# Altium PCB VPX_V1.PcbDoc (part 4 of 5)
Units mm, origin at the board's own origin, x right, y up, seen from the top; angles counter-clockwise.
Board outline 157.76 x 100.08 mm, 10 copper layers (Top Layer (PADS/SIG), Layer 2 (GND), Layer 3 (SIG), Layer 4 (SIG), Layer 5 (GND), Layer 6 (PWR), Layer 7 (GND), Layer 8 (SIG/PWR), Layer 9 (GND), Bottom Layer (PAD/SIG)), stack 1.614 mm thick; 383 components, 223 nets, 1313 pads, 1223 vias.
Unrouted connection lines stored in the file: 3.
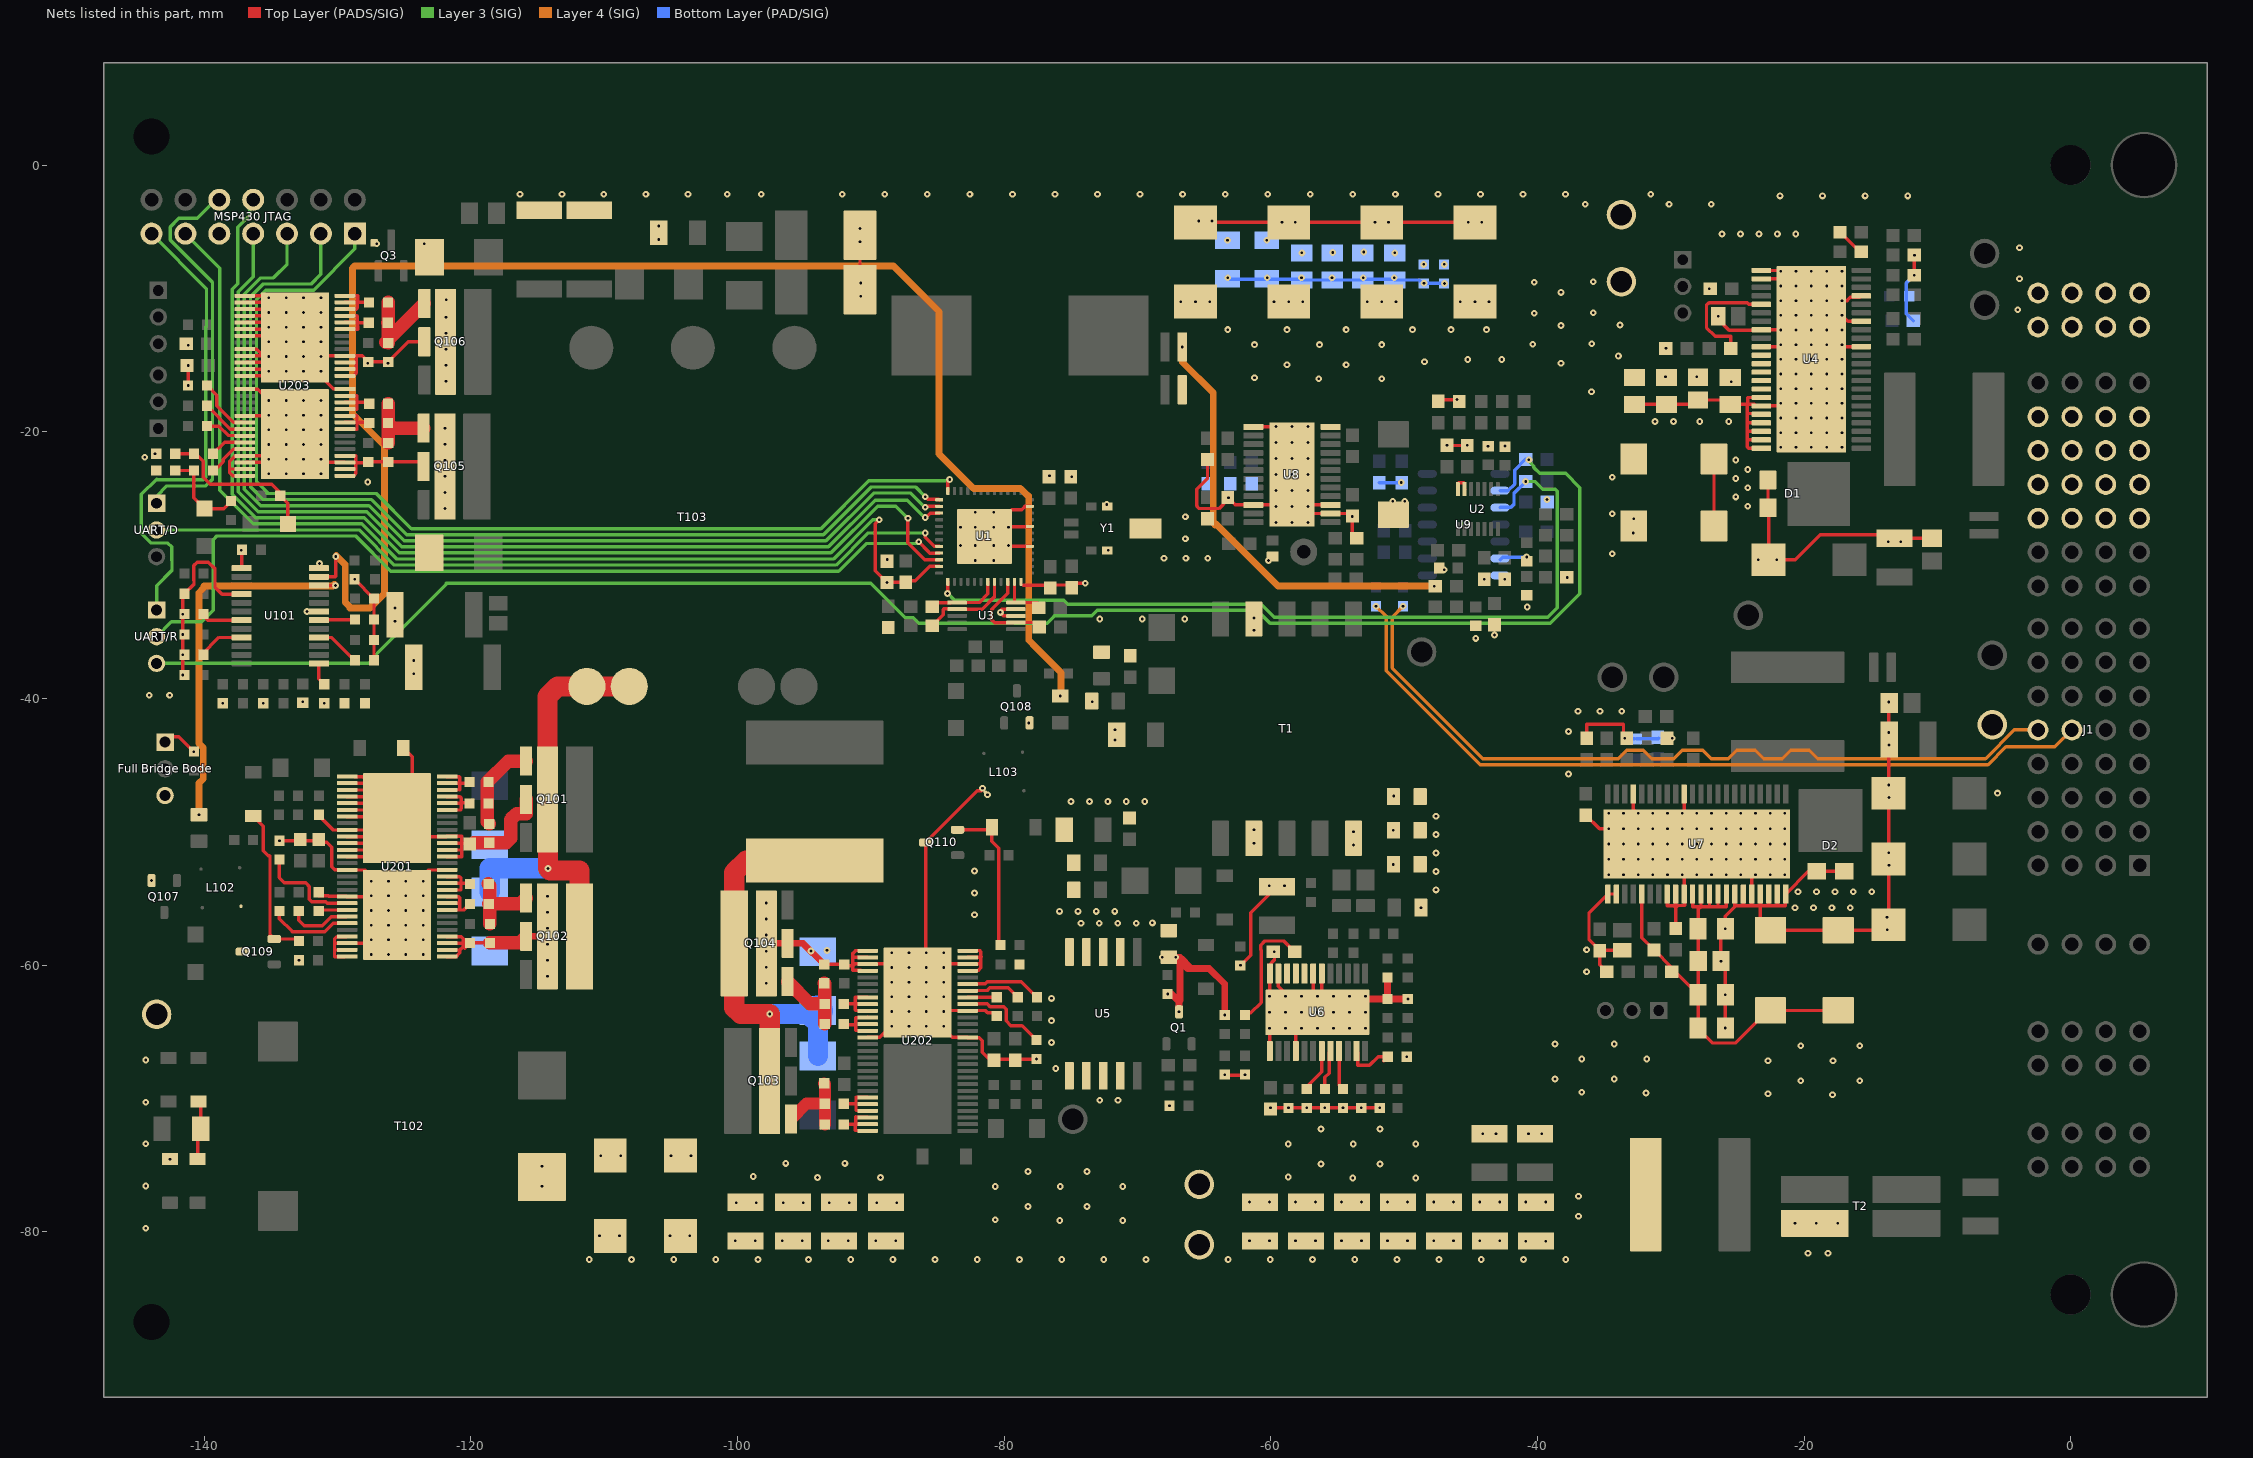
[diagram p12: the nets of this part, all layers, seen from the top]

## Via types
v1: diameter 0.508, hole 0.203, Top Layer (PADS/SIG) to Bottom Layer (PAD/SIG), 943 vias
v2: diameter 0.5, hole 0.2, Top Layer (PADS/SIG) to Bottom Layer (PAD/SIG), tented both sides, 268 vias
v3: diameter 0.5, hole 0.2, Top Layer (PADS/SIG) to Bottom Layer (PAD/SIG), 12 vias

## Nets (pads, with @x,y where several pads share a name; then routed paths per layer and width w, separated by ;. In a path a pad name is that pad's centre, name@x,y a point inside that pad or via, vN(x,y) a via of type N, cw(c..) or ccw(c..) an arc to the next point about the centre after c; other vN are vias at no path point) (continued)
NetR104_1: R104.1 U101.4 | length 3.4
  Top Layer (PADS/SIG) w0.254: U101.4@-131.381,-35.431 -130.447,-35.431 -128.741,-37.137 R104.1@-128.678,-37.137
NetR105_1: R105.1 U101.1 | length 1.7
  Top Layer (PADS/SIG) w0.254: U101.1@-131.381,-37.381 -131.381,-38.535 R105.1@-130.979,-38.937
NetR106_2: R106.2 U101.6 | length 2.7
  Top Layer (PADS/SIG) w0.254: U101.6@-131.381,-34.131 -131.339,-34.089 R106.2@-128.678,-34.089
NetR109_1: R109.1 U101.19 | length 3.2
  Top Layer (PADS/SIG) w0.254: R109.1@-140.174,-33.679 -139.722,-34.131 U101.19@-137.181,-34.131
NetR110_1: R110.1 U101.21 | length 3.5
  Top Layer (PADS/SIG) w0.254: R110.1@-140.174,-36.727 -138.878,-35.431 U101.21@-137.181,-35.431
NetR115_2: R115.2 U101.10 | length 28.5
  Top Layer (PADS/SIG) w0.254: U101.10@-131.381,-31.531 -130.143,-31.531 v1(-130.139,-31.528)
  Layer 4 (SIG) w0.508: v1@-140.441,-48.645 v1@-140.378,-48.708 ; v1@-140.378,-48.581 -140.378,-46.353 -140.051,-46.026 -140.051,-43.716 -140.385,-43.381 -140.385,-32.078 -139.997,-31.69 ; -139.997,-31.563 -130.345,-31.563 v1@-130.218,-31.436
  other v1: -140.378,-48.724
NetR116_2: R116.2 U101.11 | length 115.6
  Top Layer (PADS/SIG) w0.254: U101.11@-131.381,-30.881 -130.154,-30.881 -130.113,-30.84 v1(-130.113,-29.354)
  Layer 4 (SIG) w0.508: v1@-130.091,-29.277 -129.412,-29.956 -129.412,-32.784 -129.075,-33.121 -129.075,-33.225 -127.551,-33.225 ; -127.551,-33.214 -126.472,-32.135 -126.472,-21.053 -128.871,-18.654 -128.871,-7.737 -128.709,-7.575 -88.293,-7.575 -84.879,-10.989 -84.879,-21.657 -82.275,-24.261 -78.783,-24.261 -78.211,-24.832 -78.148,-24.832 -78.148,-35.627 -77.64,-36.135 ; -77.647,-36.142 -75.735,-38.055 v1@-75.735,-39.691
  other v1: -75.781,-39.819
NetR202_2: R202.2 U201.23 | length 6.2
  Top Layer (PADS/SIG) w0.254: R202.2@-134.344,-55.956 -134.344,-56.52 -133.393,-57.471 ; -133.393,-57.498 -130.941,-57.498 -130.314,-56.871 U201.23@-129.314,-56.871
NetR203_2: R203.2 U201.21 | length 2.1
  Top Layer (PADS/SIG) w0.254: R203.2@-131.393,-55.956 -131.308,-55.871 U201.21@-129.314,-55.871
NetR205_2: R205.2 U201.20 | length 7.8
  Top Layer (PADS/SIG) w0.254: R205.2@-134.344,-52.094 -134.367,-52.116 -134.367,-53.435 -133.976,-53.826 -132.384,-53.826 -132.101,-54.109 -132.101,-55.05 -131.909,-55.242 -130.883,-55.242 -130.753,-55.371 U201.20@-129.314,-55.371
NetR206_1: R206.1 U201.22 | length 4.7
  Top Layer (PADS/SIG) w0.254: R206.1@-132.9,-55.956 -132.9,-56.635 -132.492,-57.044 -131.129,-57.044 -130.456,-56.371 U201.22@-129.314,-56.371
NetR208_2: R208.2 U201.51 U201.52 U201.53 | length 4.8
  Top Layer (PADS/SIG) w0.254: U201.51@-121.975,-48.372 -120.752,-48.372 ; U201.52@-121.814,-47.871 -120.705,-47.871 ; U201.53@-121.814,-47.371 -120.801,-47.371 -120.705,-47.467 -120.705,-47.871 ; -120.705,-48.258 -120.705,-47.871 ; R208.2@-120.185,-47.819 -120.653,-47.819 -120.705,-47.871 ; R208.2@-120.112,-47.892 R208.2@-120.091,-47.871
NetR209_2: R209.2 U201.54 U201.55 U201.56 | length 4.6
  Top Layer (PADS/SIG) w0.254: U201.54@-121.814,-46.871 -120.955,-46.871 ; U201.55@-121.814,-46.371 -120.82,-46.371 ; U201.56@-121.814,-45.871 -120.863,-45.871 -120.82,-45.914 -120.82,-46.371 ; -120.841,-46.868 -120.82,-46.847 -120.82,-46.371 ; R209.2@-120.058,-46.295 -120.134,-46.371 -120.82,-46.371
NetR210_2: R210.2 U201.36 U201.37 U201.38 | length 4.9
  Top Layer (PADS/SIG) w0.254: U201.36@-121.814,-55.871 -120.814,-55.871 ; U201.37@-121.814,-55.371 -120.853,-55.371 -120.814,-55.411 ; U201.38@-121.814,-54.871 -120.893,-54.871 -120.814,-54.951 -120.814,-55.411 ; R210.2@-120.064,-55.41 -120.525,-55.871 -120.814,-55.871 ; -120.814,-55.871 -120.814,-55.411
NetR211_2: R211.2 U201.39 U201.40 U201.41 | length 4.9
  Top Layer (PADS/SIG) w0.254: U201.39@-121.814,-54.371 -120.725,-54.371 -120.725,-53.915 ; U201.40@-121.814,-53.871 -120.776,-53.871 ; U201.41@-121.814,-53.371 -120.836,-53.371 -120.725,-53.482 -120.725,-53.788 ; -120.693,-53.788 -120.776,-53.871 ; R211.2@-120.058,-53.915 -120.102,-53.871 -120.776,-53.871
NetR215_2: R215.2 U202.21 | length 2.2
  Top Layer (PADS/SIG) w0.254: U202.21@-82.735,-62.408 R215.2@-80.545,-62.408
NetR216_2: R216.2 U202.23 | length 5.7
  Top Layer (PADS/SIG) w0.254: U202.23@-82.735,-61.408 -81.412,-61.408 -81.25,-61.246 -78.7,-61.246 R216.2@-77.538,-62.408
NetR218_2: R218.2 U202.20 | length 6.6
  Top Layer (PADS/SIG) w0.254: U202.20@-82.735,-62.908 -81.27,-62.908 -81.055,-63.122 -80.029,-63.122 -79.837,-63.314 -79.837,-64.187 -79.486,-64.538 -78.651,-64.538 R218.2@-77.711,-65.479
NetR219_1: R219.1 U202.22 | length 4.1
  Top Layer (PADS/SIG) w0.254: U202.22@-82.735,-61.908 -81.27,-61.908 -81.062,-61.7 -79.678,-61.7 R219.1@-78.97,-62.408
NetR221_2: R221.2 U202.51 U202.52 U202.53 | length 3.7
  Top Layer (PADS/SIG) w0.254: R221.2@-92.023,-70.4 -92.012,-70.41 -91.103,-70.41 ; U202.53@-90.235,-70.908 -91.103,-70.908 -91.103,-70.41 ; U202.51@-90.235,-69.908 -91.098,-69.908 -91.103,-69.913 -91.103,-70.41
NetR222_2: R222.2 U202.54 U202.55 U202.56 | length 4.6
  Top Layer (PADS/SIG) w0.254: R222.2@-92.023,-71.948 -91.149,-71.948 ; U202.56@-90.235,-72.408 -91.135,-72.408 -91.149,-72.394 -91.149,-71.948 ; U202.55@-90.235,-71.908 -90.275,-71.948 -91.149,-71.948 ; U202.54@-90.235,-71.408 -91.093,-71.408 -91.12,-71.381 -91.12,-71.919 -91.149,-71.948
NetR223_2: R223.2 U202.36 U202.37 U202.38 | length 4.6
  Top Layer (PADS/SIG) w0.254: R223.2@-92.023,-62.908 -91.157,-62.908 ; U202.38@-90.235,-63.408 -91.116,-63.408 -91.157,-63.367 -91.157,-62.908 ; U202.37@-90.235,-62.908 -91.157,-62.908 ; U202.36@-90.235,-62.408 -91.139,-62.408 -91.157,-62.425 -91.157,-62.908
NetR224_2: R224.2 U202.39 U202.40 U202.41 | length 3.7
  Top Layer (PADS/SIG) w0.254: R224.2@-92.023,-64.408 -91.942,-64.489 -91.116,-64.489 ; U202.41@-90.235,-64.908 -91.116,-64.908 -91.116,-64.489 ; U202.39@-90.235,-63.908 -90.26,-63.933 -91.116,-63.933 -91.116,-64.489
NetR228_1: R228.1 U203.22 | length 3.1
  Top Layer (PADS/SIG) w0.254: R228.1@-139.767,-19.579 -138.885,-19.579 -138.183,-20.281 -136.956,-20.281 U203.22@-136.933,-20.304
NetR229_2: R229.2 U203.21 | length 3.6
  Top Layer (PADS/SIG) w0.254: R229.2@-139.767,-18.055 -138.018,-19.804 U203.21@-136.933,-19.804
NetR230_1: R230.1 U203.20 | length 4.5
  Top Layer (PADS/SIG) w0.254: R230.1@-139.767,-16.531 -139.036,-17.263 -139.036,-18.061 -137.792,-19.304 U203.20@-136.933,-19.304
NetR231_2: R231.2 U203.51 U203.52 U203.53 | length 4.7
  Top Layer (PADS/SIG) w0.254: U203.51@-129.433,-12.304 -129.414,-12.323 -128.474,-12.323 -128.474,-12.081 -128.493,-12.062 -128.493,-11.82 ; U203.52@-129.433,-11.804 -128.508,-11.804 -128.493,-11.82 ; U203.53@-129.433,-11.304 -128.524,-11.304 -128.493,-11.336 -128.493,-11.82 ; R231.2@-127.641,-11.828 -127.649,-11.82 -128.493,-11.82
NetR232_2: R232.2 U203.54 U203.55 U203.56 | length 4.7
  Top Layer (PADS/SIG) w0.254: U203.54@-129.433,-10.804 -128.572,-10.804 -128.493,-10.725 -128.493,-10.304 ; U203.55@-129.433,-10.304 -128.493,-10.304 ; U203.56@-129.433,-9.804 -128.474,-9.804 -128.474,-10.286 -128.493,-10.304 ; R232.2@-127.619,-10.304 -128.493,-10.304
NetR233_2: R233.2 U203.36 U203.37 U203.38 | length 4.7
  Top Layer (PADS/SIG) w0.254: U203.36@-129.433,-19.804 -128.524,-19.804 -128.524,-19.304 ; U203.37@-129.433,-19.304 -128.524,-19.304 ; U203.38@-129.433,-18.804 -128.524,-18.804 -128.524,-19.304 ; R233.2@-127.611,-19.354 -127.661,-19.304 -128.524,-19.304
NetR234_2: R234.2 U203.39 U203.40 U203.41 | length 4.7
  Top Layer (PADS/SIG) w0.254: U203.39@-129.433,-18.304 -128.549,-18.304 -128.524,-18.28 -128.524,-17.792 ; U203.40@-129.433,-17.804 -129.414,-17.786 -128.531,-17.786 -128.524,-17.792 ; U203.41@-129.433,-17.304 -128.524,-17.304 -128.524,-17.792 ; R234.2@-127.611,-17.905 -127.724,-17.792 -128.524,-17.792
NetR237_2: R237.2 U203.23 | length 2.4
  Top Layer (PADS/SIG) w0.254: R237.2@-139.338,-21.658 -138.461,-20.781 U203.23@-137.33,-20.781
NetR238_2: R238.2 U203.24 | length 3.1
  Top Layer (PADS/SIG) w0.254: R238.2@-139.235,-22.927 -138.546,-22.238 -138.546,-22.059 -137.814,-21.327 -136.933,-21.327 U203.24@-136.933,-21.304
NetU1_20: U1.20 UART/D.2 | length 61.4
  Top Layer (PADS/SIG) w0.254: v1(-85.91,-27.593) -85.91,-27.914 -85.221,-28.603 U1.20@-84.868,-28.603
  Layer 3 (SIG) w0.254: UART/D.2@-143.553,-27.372 -140.632,-27.372 ; -140.632,-27.368 -128.367,-27.368 -125.735,-29.999 -92.601,-29.999 -90.195,-27.593 v1(-85.91,-27.593)
NetU1_21: U1.21 UART/R.2 | length 67.1
  Top Layer (PADS/SIG) w0.254: v1(-86.403,-28.261) -85.641,-29.023 ; -85.58,-29.103 U1.21@-84.868,-29.103
  Layer 3 (SIG) w0.254: UART/R.2@-143.553,-35.373 -142.44,-34.26 -140.161,-34.26 -139.308,-33.407 -139.308,-28.088 -139.042,-27.822 -128.625,-27.822 -125.993,-30.453 -92.413,-30.453 -90.348,-28.388 v1@-86.403,-28.388
NetU2_13: U2.13 U2.14 | length 0.9
  Top Layer (PADS/SIG) w0.254: U2.14@-45.969,-24.305 -45.969,-23.893 -45.892,-23.816 U2.13@-45.509,-23.816 ; U2.13@-45.469,-24.324 U2.13@-45.446,-24.324
nRST: "MSP430 JTAG.11" C5.2 R24.2 U1.23 | length 82.7
  Top Layer (PADS/SIG) w0.254: v1(-89.359,-26.61) -89.662,-26.912 -89.662,-30.429 v1(-88.778,-31.313) -88.759,-31.294 R24.2@-87.673,-31.294 ; R24.2@-87.673,-31.182 R24.2@-87.383,-31.182 ; R24.2@-87.383,-31.294 -87.271,-31.182 -86.657,-31.182 -85.578,-30.103 U1.23@-84.868,-30.103
  Layer 3 (SIG) w0.254: -141.394,-5.147 -138.854,-7.687 -138.809,-7.732 -138.809,-24.399 -136.294,-26.914 -128.179,-26.914 -125.547,-29.545 -92.789,-29.545 -89.854,-26.61 v1(-89.359,-26.61)
OUTA: D113.1 Q109.2 R204.2 | length 11.9
  Top Layer (PADS/SIG) w0.254: D113.1@-136.314,-48.822 -135.552,-49.584 -135.552,-51.416 -135.171,-51.797 -135.085,-51.797 -135.052,-51.83 -135.052,-57.726 Q109.2@-134.733,-58.045 -133.073,-58.045 R204.2@-132.885,-58.233
OUTB: D114.1 Q110.2 R217.2 | length 11.7
  Top Layer (PADS/SIG) w0.254: Q110.2@-83.482,-49.856 -83.477,-49.851 D114.1@-80.912,-49.851 ; D114.1@-80.912,-49.668 D114.1@-80.912,-49.851 ; D114.1@-80.815,-49.851 D114.1@-80.912,-49.851 ; R217.2@-80.307,-58.487 -80.39,-58.404 -80.39,-51.251 -80.912,-50.729 D114.1@-80.912,-49.851
PGND: C1.1 C2.1 C7.2 C8.2 C9.2 C10.2 C11.2 C12.2 C13.2 C19.2 C20.2 C38.2 C39.2 C40.2 C41.2 C42.2 C43.2 C48.2 C49.2 C50.1 C51.1 C52.1 C53.1 C54.2 C55.2 C56.2 C57.1 C102.2 C103.2 C107.2 C108.2 C201.2 C202.1 C205.1 C206.2 C207.1 C210.1 C305.1 C306.1 D9.2 D10.2 L102.3 L103.3 PGND_1.1 Q102.4 Q102.5 Q104.4 Q104.5 Q109.3 Q110.3 R48.1 R52.1 R53.1 R58.1 R59.1 R60.1 R63.1 R64.1 R65.1 R66.1 R203.1 R205.1 R213.2 R215.1 R218.1 R226.2 T1.2 T2.4 U5.2 U5.3 U5.4 U5.5 U5.6 U5.7 U5.8 U5.9 U6.6 U6.7 U6.11 U6.12 U6.13 U6.16 U6.25 U201.15 U201.19 U201.25 U201.26 U201.27 U201.28 U201.29 U201.30 U201.31 U201.32 U201.42 U201.58 U202.15 U202.19 U202.25 U202.26 U202.27 U202.28 U202.29 U202.30 U202.31 U202.32 U202.42 U202.58 | length 124.6
  Top Layer (PADS/SIG) w0.254: v1(-134.344,-50.671) -131.393,-50.671 -131.393,-50.793 -130.793,-50.793 -130.416,-51.169 -130.416,-52.628 -130.195,-52.848 -129.337,-52.848 -129.314,-52.871 -127.958,-52.871 U201.58@-127.39,-53.44 ; R203.1@-131.393,-54.534 -131.393,-54.788 -130.695,-54.788 -130.634,-54.848 U201.19@-129.314,-54.848 ; U201.28@-129.456,-59.376 -130.218,-59.376 -130.218,-58.868 ; U201.27@-129.314,-58.871 -130.215,-58.871 -130.218,-58.868 ; U201.25@-129.314,-57.871 -130.03,-57.871 -130.218,-58.059 -130.218,-58.36 ; U201.19@-129.314,-54.871 -127.745,-54.871 U201.58@-127.678,-54.804 ; U201.58@-127.669,-54.813 U201.58@-127.39,-54.534 ; U201.58@-127.424,-57.852 -127.943,-58.371 -130.207,-58.371 -130.218,-58.36 ; U201.58@-123.686,-53.424 -123.134,-52.871 U201.42@-121.814,-52.871 ; U201.29@-121.814,-59.371 -121.103,-59.371 -120.814,-59.083 -120.814,-58.871 ; U201.30@-121.814,-58.871 -120.814,-58.871 ; U201.31@-121.814,-58.371 -120.795,-58.371 ; U201.32@-121.814,-57.871 -120.712,-57.871 -120.566,-58.018 -120.566,-58.624 -120.814,-58.871 ; -120.712,-58.341 -120.693,-58.36 ; -120.456,-58.724 C205.1@-120.064,-58.333 R213.2@-118.564,-58.333 ; R226.2@-93.485,-59.946 C210.1@-91.985,-59.946 -91.881,-60.05 -91.356,-60.05 ; -91.356,-59.122 -91.356,-60.05 ; -91.315,-59.111 -91.111,-58.908 U202.29@-90.235,-58.908 ; -91.244,-59.408 U202.30@-90.235,-59.408 ; U202.32@-90.721,-60.431 -90.76,-60.392 -91.356,-60.392 -91.356,-60.05 ; U202.42@-90.235,-65.408 -89.315,-65.408 -86.485,-62.578 -86.485,-62.033 -88.61,-59.908 -91.172,-59.908 -91.315,-60.05 -91.356,-60.05 ; U202.58@-85.768,-59.249 -85.882,-59.135 Q110.3@-85.882,-50.806 -82.006,-46.93 v1@-81.704,-46.93 ; U202.58@-84.607,-64.685 -83.884,-65.408 U202.15@-82.804,-65.408 ; U202.58@-84.607,-63.59 -84.425,-63.408 -81.412,-63.408 -81.243,-63.576 -80.799,-63.576 R215.1@-80.545,-63.83 ; U202.58@-84.607,-60.305 -84.21,-59.908 -82.735,-59.908 -82.733,-59.91 -81.74,-59.91 ; U202.25@-82.735,-60.408 -81.933,-60.408 -81.74,-60.215 -81.74,-59.91 ; U202.27@-82.735,-59.408 -81.736,-59.408 -81.704,-59.376 ; U202.28@-82.735,-58.908 -81.828,-58.908 -81.74,-58.995 -81.74,-59.376 ; U202.15@-82.733,-65.428 -82.71,-65.451 -81.851,-65.451 -81.631,-65.671 -81.631,-66.548 -81.041,-67.138 C207.1@-80.76,-67.138 ; -81.74,-59.503 -81.74,-59.91 ; C207.1@-80.76,-67.049 v1(-77.56,-67.049) ; R52.1@-63.289,-68.266 -61.965,-68.266 v1(-61.933,-68.235) ; C52.1@-62.281,-60.04 -61.511,-59.269 -61.511,-56.074 -59.556,-54.119 R59.1@-59.514,-54.119 ; U6.25@-60.114,-62.297 -60.074,-62.257 U6.12@-60.074,-60.643 ; U6.12@-60.114,-60.011 -59.717,-59.614 C42.2@-59.717,-58.998 ; v2(-60.099,-64.743) -60.074,-64.768 U6.13@-60.074,-66.443 ; v1(-60.022,-70.711) v1(-58.676,-70.711) v1(-57.299,-70.711) v1(-54.585,-70.711) v1(-53.207,-70.711) v1(-51.819,-70.711) ; U6.11@-59.424,-60.643 -59.424,-61.59 U6.25@-58.971,-62.043 ; U6.16@-58.124,-66.443 -58.124,-65.168 v2(-57.699,-64.743) ; U6.7@-56.824,-60.643 -56.824,-62.031 U6.25@-56.558,-62.297 ; U6.25@-56.177,-62.297 -56.174,-62.294 U6.6@-56.174,-60.643 ; -130.218,-58.868 -130.218,-58.36
  Top Layer (PADS/SIG) w0.508: Q102.5@-115.842,-57.846 Q102.4@-114.241,-57.846 ; Q104.4@-97.834,-58.369 Q104.5@-96.233,-58.369 -95.063,-58.369 R226.2@-93.485,-59.946 ; v2(-52.899,-62.343) -52.689,-62.553 C56.2@-51.249,-62.553 ; C48.2@-51.249,-60.927 C56.2@-51.249,-62.553 ; C55.2@-49.725,-62.553 C56.2@-51.249,-62.553
  Top Layer (PADS/SIG) w1.016: R213.2@-118.564,-58.333 -116.328,-58.333 Q102.5@-115.842,-57.846
  other v1: -111.107,-82.074 -107.943,-82.074 -104.779,-82.074 -101.615,-82.074 -98.45,-82.074 -94.666,-82.074 -91.502,-82.074 -88.338,-82.074 -85.174,-82.074 -82.009,-82.074 -78.845,-82.074 -75.681,-82.074 -72.517,-82.074 -69.352,-82.074 -63.196,-82.074 -60.032,-82.074 -56.867,-82.074 -53.703,-82.074 -50.539,-82.074 -47.375,-82.074 -44.21,-82.074 -41.046,-82.074 -37.882,-82.074 -19.704,-81.614 -18.206,-81.614 -40.871,-80.703 -39.373,-80.703 -100.168,-80.675 -98.67,-80.675 -96.633,-80.675 -95.135,-80.675 -93.182,-80.675 -91.685,-80.675 -89.626,-80.675 -88.129,-80.675 -61.597,-80.675 -60.099,-80.675 -58.144,-80.675 -56.646,-80.675 -54.691,-80.675 -53.193,-80.675 -51.238,-80.675 -49.74,-80.675 -47.785,-80.675 -46.287,-80.675 -44.332,-80.675 -42.835,-80.675 -110.333,-80.305 -108.835,-80.305 -105.06,-80.305 -103.562,-80.305 -20.69,-79.372 -19.082,-79.372 -17.474,-79.372 -44.109,-72.65 -43.101,-72.65 -40.675,-72.65 -39.667,-72.65 -55.941,-70.711 -67.591,-70.555 -72.832,-70.141 -71.45,-70.141 -63.451,-68.218 -76.116,-67.758 -49.803,-66.879 -76.439,-65.808 -76.439,-64.167 -49.7,-62.551 -76.437,-62.497 -97.834,-61.354 -114.241,-60.831 -97.834,-60.154 -62.273,-60.011 -132.873,-59.637 -114.241,-59.631 -137.076,-58.995 -59.733,-58.995 -97.834,-58.953 -94.485,-58.946 -93.276,-58.898 -114.241,-58.43 -97.834,-57.753 -114.241,-57.23 -74.235,-56.861 -72.853,-56.861 -71.471,-56.861 -70.089,-56.861 -68.877,-56.836 -97.834,-56.552 -82.218,-56.231 -114.241,-56.029 -75.844,-55.972 -74.462,-55.972 -73.08,-55.972 -71.698,-55.972 -48.735,-55.696 -97.834,-55.352 -114.241,-54.829 -82.218,-54.59 -47.605,-54.361 -60.114,-54.042 -58.971,-54.042 -47.605,-52.98 -82.218,-52.948 -47.605,-51.598 -61.257,-50.867 -47.605,-50.216 -61.257,-49.851 -47.605,-48.834 -74.977,-47.728 -73.595,-47.728 -72.213,-47.728 -70.831,-47.728 -69.449,-47.728 -81.249,-47.222 -81.61,-46.737
  other v2: -58.899,-64.743 -56.499,-64.743 -55.299,-64.743 -54.099,-64.743 -52.899,-64.743 -88.433,-64.578 -87.133,-64.578 -85.833,-64.578 -84.533,-64.578 -60.099,-63.543 -58.899,-63.543 -57.699,-63.543 -56.499,-63.543 -55.299,-63.543 -54.099,-63.543 -52.899,-63.543 -88.433,-63.478 -87.133,-63.478 -85.833,-63.478 -84.533,-63.478 -88.433,-62.378 -87.133,-62.378 -85.833,-62.378 -84.533,-62.378 -60.099,-62.343 -58.899,-62.343 -57.699,-62.343 -56.499,-62.343 -55.299,-62.343 -54.099,-62.343 -88.433,-61.278 -87.133,-61.278 -85.833,-61.278 -84.533,-61.278 -88.433,-60.178 -87.133,-60.178 -85.833,-60.178 -84.533,-60.178 -127.465,-59.209 -126.165,-59.209 -124.865,-59.209 -123.565,-59.209 -88.433,-59.078 -87.133,-59.078 -85.833,-59.078 -84.533,-59.078 -127.465,-58.109 -126.165,-58.109 -124.865,-58.109 -123.565,-58.109 -127.465,-57.009 -126.165,-57.009 -124.865,-57.009 -123.565,-57.009 -127.465,-55.909 -126.165,-55.909 -124.865,-55.909 -123.565,-55.909 -127.465,-54.809 -126.165,-54.809 -124.865,-54.809 -123.565,-54.809 -127.465,-53.709 -126.165,-53.709 -124.865,-53.709 -123.565,-53.709
PVIN: 12V.1 "Full Bridge Bode.1" C17.2 C18.2 C21.1 C22.1 C23.1 C24.1 C58.2 C59.2 C62.1 C63.1 C64.1 C65.1 C115.1 C116.1 C119.1 C120.1 C121.1 C123.1 C124.1 C125.1 C301.1 C302.1 C303.1 C304.1 D101.1 J1.P6 R1.2 R2.2 R8.2 R33.2 R36.2 R43.2 R124.2 U4.5 U4.11 U4.12 U4.13 U4.14 U4.15 U7.5 U7.11 U7.12 U7.13 U7.14 U7.15 | length 98
  Top Layer (PADS/SIG) w0.254: -142.791,-42.866 -141.902,-42.866 v1(-140.759,-44.009) ; U7.5@-32.176,-54.674 -32.176,-57.947 R43.2@-31.255,-58.867 -29.921,-60.201 R36.2@-29.921,-60.51 -29.668,-60.51 C65.1@-27.942,-62.236 ; U7.11@-28.366,-54.674 -28.366,-55.616 -27.731,-55.616 ; U7.12@-27.731,-54.674 -27.731,-55.616 ; U7.13@-27.096,-54.674 -27.096,-55.616 ; U7.14@-26.461,-54.674 -26.461,-55.594 -26.438,-55.616 ; U7.15@-25.826,-54.674 -25.826,-55.611 -25.832,-55.616 -26.438,-55.616 ; R33.2@-25.508,-13.758 -25.508,-12.833 -26.678,-12.833 -27.324,-12.187 -27.324,-10.516 -27.132,-10.325 -24.261,-10.325 -24.139,-10.447 U4.5@-23.204,-10.448 ; C58.2@-17.438,-63.403 C59.2@-22.524,-63.403 -22.701,-63.403 -25.139,-65.842 -26.906,-65.842 -27.942,-64.805 C62.1@-27.942,-64.714 C65.1@-27.942,-62.236 ; C65.1@-27.942,-62.236 C63.1@-27.942,-57.278 -27.942,-55.827 -27.731,-55.616 ; -27.731,-55.616 -27.096,-55.616 ; -27.096,-55.616 -26.438,-55.616
  Layer 4 (SIG) w0.508: v1(-66.636,-13.648) -66.636,-14.768 -64.305,-17.1 -64.305,-26.864 -64.178,-26.991 ; -64.108,-26.921 -59.465,-31.563 v1@-47.795,-31.563
  Bottom Layer (PAD/SIG) w0.254: C119.1@-63.242,-8.533 -63.199,-8.576 C120.1@-60.368,-8.576 ; C120.1@-60.303,-8.533 -60.26,-8.576 C301.1@-57.664,-8.576 ; C301.1@-57.664,-8.62 -55.586,-8.62 C302.1@-55.542,-8.576 ; C302.1@-55.378,-8.62 C303.1@-53.212,-8.62 ; C303.1@-53.092,-8.62 -53.048,-8.576 C304.1@-50.703,-8.576 ; C304.1@-50.703,-8.62 -48.894,-8.62 C116.1@-48.58,-8.934 ; C116.1@-48.52,-8.874 -47.116,-8.874 C115.1@-47.033,-8.957
  other v1: -142.55,-74.555 -17.873,-69.72 -22.701,-69.655 -31.855,-69.598 -36.683,-69.533 -20.259,-68.67 -15.825,-68.67 -38.686,-68.548 -34.241,-68.548 -22.701,-67.169 -17.828,-67.169 -36.683,-67.047 -31.809,-67.047 -20.259,-66.044 -15.825,-66.044 -38.686,-65.922 -34.241,-65.922 -47.746,-31.589 -34.393,-29.158 -32.821,-27.595 -32.781,-26.535 -34.393,-26.147 -34.393,-23.418 -35.941,-17.007 -25.468,-16.249 -56.394,-16.021 -51.67,-16.021 -61.222,-15.957 -30.401,-15.883 -28.052,-15.886 -58.78,-14.971 -54.346,-14.971 -38.226,-14.872 -48.474,-14.746 -45.229,-14.588 -42.678,-14.588 -33.928,-14.325 -61.222,-13.47 -56.349,-13.47 -51.67,-13.47 -40.355,-13.444 -35.931,-13.405 -63.225,-12.345 -58.78,-12.345 -54.346,-12.345 -49.363,-12.345 -46.481,-12.345 -43.826,-12.345 -38.227,-12.037 -33.802,-11.998 -40.23,-11.117 -35.805,-11.078 -3.97,-10.86 -66.739,-10.249 -65.64,-10.249 -64.58,-10.249 -59.754,-10.249 -58.655,-10.249 -57.595,-10.249 -52.769,-10.249 -51.67,-10.249 -50.61,-10.249 -45.784,-10.249 -44.685,-10.249 -43.625,-10.249 -38.227,-9.551 -46.97,-8.888 -48.512,-8.866 -40.23,-8.789 -35.805,-8.75 -3.845,-8.534 -63.218,-8.449 -60.262,-8.449 -57.701,-8.449 -55.399,-8.449 -53.07,-8.449 -50.737,-8.449 -3.845,-6.205
R: R26.2 U9.2 UART/R.3 | length 128.7
  Layer 3 (SIG) w0.254: UART/R.3@-143.553,-37.373 -127.646,-37.373 -127.424,-37.151 ; -127.487,-37.088 -121.836,-31.436 -121.836,-31.361 -90.002,-31.361 -87.402,-33.961 -86.797,-33.961 -86.403,-34.355 -76.749,-34.355 -76.243,-33.849 ; -76.243,-33.812 -73.417,-33.812 -73,-33.395 -61.016,-33.395 -60.054,-34.357 -39.025,-34.357 -36.819,-32.151 -36.819,-24.196 -37.889,-23.126 -39.838,-23.126 -40.278,-22.686 -40.278,-22.587 v1@-40.767,-22.098
  Bottom Layer (PAD/SIG) w0.254: U9.2@-42.809,-24.424 -42.212,-24.424 -41.712,-23.924 -41.712,-22.881 -40.91,-22.079 -40.786,-22.079 R26.2@-40.767,-22.098
  other v1: -40.64,-22.098
RE: R25.2 U1.25 U9.3 | length 62.3
  Top Layer (PADS/SIG) w0.254: v1(-84.234,-32.132) -84.218,-32.116 U1.25@-84.218,-31.253
  Layer 3 (SIG) w0.254: v1(-84.234,-32.132) -83.716,-32.65 -75.526,-32.65 -75.235,-32.941 -60.695,-32.941 -59.733,-33.903 -39.213,-33.903 -38.525,-33.215 -38.525,-25.594 ; v1(-40.885,-23.739) -40.175,-23.739 -39.59,-24.324 -38.651,-24.324 -38.524,-24.451 -38.524,-25.594
  Bottom Layer (PAD/SIG) w0.254: U9.3@-42.809,-25.694 -42.809,-25.663 -41.982,-25.663 -41.757,-25.438 -41.757,-24.611 v1(-40.885,-23.739)
REFCAP: C54.1 U6.20 | length 3
  Top Layer (PADS/SIG) w0.254: C54.1@-55.941,-69.289 -55.941,-68.42 -55.622,-68.101 -55.622,-66.541 U6.20@-55.524,-66.443
RS485_N: J1.D5 R82.2 | length 59.7
  Layer 4 (SIG) w0.254: v1(-50.081,-33.087) -50.897,-33.903 -50.897,-37.725 -44.105,-44.517 ; -44.039,-44.517 -33.952,-44.517 -33.317,-43.882 -32.047,-43.882 -31.412,-44.517 -29.761,-44.517 -29.126,-43.882 -27.602,-43.882 -26.967,-44.517 -25.697,-44.517 -25.062,-43.882 -23.665,-43.882 -23.03,-44.517 -21.633,-44.517 -20.998,-43.882 -19.601,-43.882 -18.966,-44.517 -6.393,-44.517 -4.234,-42.358 J1.D5@-1.948,-42.358
RS485_P: J1.C5 R81.2 | length 60.7
  Layer 4 (SIG) w0.254: v1(-52.113,-33.087) -51.351,-33.849 -51.351,-37.913 -44.293,-44.971 -17.623,-44.971 ; -17.569,-44.971 -6.205,-44.971 -4.862,-43.628 -1.186,-43.628 J1.C5@0.211,-42.231
RSC: R65.2 U6.23 | length 4.1
  Top Layer (PADS/SIG) w0.254: U6.23@-53.574,-66.443 -53.476,-66.541 -53.476,-67.52 -52.592,-67.52 -51.951,-66.879 R65.2@-51.226,-66.879 R65.2@-51.534,-67.187
RT: R64.2 U6.19 | length 3.3
  Top Layer (PADS/SIG) w0.254: R64.2@-57.299,-69.289 -57.299,-69.137 -56.174,-68.011 U6.19@-56.174,-66.443
SCL: R18.2 U1.32 U3.2 | length 7
  Top Layer (PADS/SIG) w0.254: R18.2@-85.394,-34.542 -85.372,-34.542 -84.567,-33.738 -84.567,-33.341 -84.516,-33.29 -83.804,-33.29 U3.2@-83.736,-33.29 ; U3.2@-83.736,-33.336 -83.514,-33.336 U3.2@-83.514,-33.313 -81.652,-33.313 -80.718,-32.38 U1.32@-80.718,-31.253
SDA: R19.2 U1.31 U3.1 | length 5.7
  Top Layer (PADS/SIG) w0.254: R19.2@-85.394,-33.128 -85.325,-33.128 -85.325,-32.836 -83.992,-32.836 -83.969,-32.813 U3.1@-83.514,-32.813 -81.864,-32.813 -81.218,-32.168 U1.31@-81.218,-31.253
SGND: "Full Bridge Bode.3" "MSP430 JTAG.9" C3.2 C4.2 C5.1 C14.1 C15.2 C16.1 C17.1 C18.1 C21.2 C22.2 C23.2 C24.2 C25.2 C26.2 C27.2 C28.1 C29.2 C30.2 C31.2 C32.2 C33.1 C34.2 C35.2 C36.2 C44.2 C45.1 C46.1 C58.1 C59.1 C60.1 C62.2 C63.2 C64.2 C65.2 C66.2 C67.2 C68.2 C70.2 C73.2 C74.1 C75.2 C76.2 C77.2 C88.2 C89.2 C90.2 C91.2 C92.2 C93.2 C94.2 C95.2 C96.2 C97.2 C98.2 C99.1 C100.2 C101.2 C104.1 C105.1 C106.2 C109.1 C110.2 C111.2 C112.2 C113.1 C114.1 C115.2 C116.2 C119.2 C120.2 C121.2 C122.2 C123.2 C124.2 C125.2 C126.2 C127.2 C128.1 C129.2 C211.2 C212.1 C213.1 C214.1 C301.2 C302.2 C303.2 C304.2 D1.1 D1.2 D2.1 D2.2 D103.2 D104.2 D106.2 D107.2 J1.P4 J1.P5 Q3.4 Q105.4 Q105.5 Q106.4 Q106.5 Q107.2 Q108.2 R6.2 R7.2 R13.2 R27.2 R28.2 R29.2 R30.2 R34.2 R39.2 R40.1 R42.1 R45.1 R54.1 R69.2 R70.1 R72.1 R75.1 R76.2 R79.1 R101.1 R102.1 R103.1 R104.2 R105.2 R106.1 R109.2 R110.2 R117.1 R118.1 R119.1 R120.1 R121.2 R126.1 R230.2 R235.2 R236.2 R301.2 SGND.1 SGND_1.1 SGND_3.1 T1.9 U1.36 U1.41 U1.44 U1.47 U1.49@-81.468,-27.853 U3.8 U3.9 U4.1 U4.2 U4.8 U4.10 U4.16 U4.17 U4.18 U4.19 U4.20 U4.21 U4.22 U4.35 U4.38 U4.41 U4.45 U7.1 U7.2 U7.8 U7.9 U7.10 U7.16 U7.17 U7.18 U7.19 U7.20 U7.21 U7.22 U7.35 U7.41 U7.45 U8.1 U8.10 U8.14 U8.15 U8.24 U8.25 U9.6 U9.7 U101.7 U101.12 U101.13 U101.16 U203.1 U203.2 U203.3 U203.4 U203.5 U203.6 U203.7 U203.9 U203.10 U203.11 U203.12 U203.13 U203.15 U203.19 U203.25 U203.26 U203.27 U203.28 U203.29 U203.30 U203.31 U203.32 U203.42 U203.44 U203.45 U203.46 U203.47 U203.57 U203.58 Y1.3 | length 308.2
  Top Layer (PADS/SIG) w0.254: v1(-141.597,-38.251) v1(-141.597,-36.727) v1(-141.597,-35.203) v1(-141.597,-33.679) C110.2@-141.597,-32.155 ; C110.2@-141.47,-32.155 -140.75,-31.436 -140.75,-31.153 -140.755,-31.148 -140.755,-30.035 -140.505,-29.785 -139.669,-29.785 -139.175,-30.279 -139.175,-31.657 -138.65,-32.181 U101.16@-137.181,-32.181 ; v1(-141.19,-16.531) v1(-141.19,-15.032) ; D103.2@-140.482,-74.555 -140.482,-72.515 R103.1@-140.25,-72.283 -140.25,-70.398 D104.2@-140.407,-70.241 ; U203.25@-137.584,-21.804 U203.25@-136.933,-21.804 -135.191,-21.804 U203.58@-135.171,-21.784 ; U203.25@-137.584,-21.784 -137.629,-21.784 -138.092,-22.247 -138.092,-22.8 ; U101.13@-137.181,-30.231 -137.181,-28.85 C104.1@-137.16,-28.829 ; U203.27@-137.076,-22.8 -138.092,-22.8 ; U203.26@-136.933,-22.304 -135.437,-22.304 U203.58@-135.171,-22.038 ; U203.19@-136.933,-18.804 -135.183,-18.804 v2(-135.133,-18.754) ; U203.15@-136.933,-16.804 -135.983,-16.804 v2(-135.133,-17.654) ; U203.13@-136.933,-15.804 -135.483,-15.804 v2(-135.133,-15.454) -135.283,-15.304 U203.12@-136.933,-15.304 ; U203.11@-136.933,-14.804 -135.583,-14.804 v2(-135.133,-14.354) ; U203.10@-136.933,-14.304 U203.57@-135.183,-14.304 ; U203.9@-136.933,-13.804 -136.039,-13.804 U203.57@-135.552,-14.291 ; U203.7@-136.933,-12.804 -133.308,-12.804 U203.57@-133.183,-12.929 -133.183,-13.913 -130.314,-16.781 -129.456,-16.781 U203.42@-129.433,-16.804 ; U203.6@-136.933,-12.304 -135.283,-12.304 v2(-135.133,-12.154) -135.483,-11.804 U203.5@-136.933,-11.804 ; U203.4@-136.933,-11.304 -135.383,-11.304 v2(-135.133,-11.054) -135.383,-10.804 U203.3@-136.933,-10.804 ; U203.2@-136.933,-10.304 -135.483,-10.304 v2(-135.133,-9.954) -135.283,-9.804 U203.1@-136.933,-9.804 ; U203.28@-136.822,-23.308 -137.838,-23.308 -138.092,-23.054 -138.092,-22.8 ; v2(-131.233,-22.054) -130.983,-22.304 U203.31@-129.433,-22.304 ; v2(-131.233,-14.354) -131.183,-14.304 U203.47@-129.433,-14.304 -128.572,-14.304 ; U203.29@-129.433,-23.304 -128.778,-23.304 -128.612,-23.138 -128.612,-22.34 ; U203.32@-129.433,-21.804 -128.612,-21.804 -128.612,-22.34 ; U203.44@-129.433,-15.804 -128.78,-15.804 -128.572,-15.596 -128.572,-14.304 ; v1(-128.704,-31.071) -128.702,-31.071 R76.2@-127.256,-32.517 R106.1@-127.256,-34.089 C105.1@-127.256,-35.613 R104.2@-127.256,-37.137 ; Q105.5@-123.795,-22.605 Q105.5@-123.531,-22.605 -123.871,-22.265 R236.2@-126.183,-22.265 C214.1@-127.683,-22.265 -127.757,-22.34 -128.612,-22.34 ; Q106.5@-123.477,-13.256 -124.673,-13.256 R235.2@-126.183,-14.765 C213.1@-127.683,-14.765 -128.144,-14.304 -128.572,-14.304 ; R121.2@-90.8,-5.263 -90.8,-9.299 R301.2@-90.75,-9.349 ; U1.49@-80.688,-27.118 -79.413,-25.843 -78.661,-25.843 ; v1@-80.18,-33.468 -80.18,-33.691 -80.072,-33.799 ; -80.18,-33.313 U3.9@-79.114,-33.313 ; -80.059,-33.813 U3.8@-79.114,-33.813 ; U1.49@-79.672,-28.515 -79.584,-28.603 U1.41@-78.068,-28.603 ; U1.49@-79.545,-27.118 -78.083,-27.118 U1.44@-78.068,-27.103 ; -78.602,-25.784 -78.474,-25.656 -78.439,-25.656 -78.439,-25.603 U1.47@-78.068,-25.603 ; -78.579,-31.503 -76.764,-31.503 C3.2@-76.544,-31.723 -76.316,-31.494 -74.93,-31.494 -74.805,-31.369 v1(-73.914,-31.369) ; C124.2@-65.64,-4.299 C125.2@-58.655,-4.299 C123.2@-44.685,-4.299 ; R27.2@-64.739,-22.083 -64.739,-23.498 -65.541,-24.3 -65.541,-25.571 -65.35,-25.762 -63.88,-25.762 -63.215,-25.098 R29.2@-63.215,-24.935 -62.662,-25.488 U8.10@-61.306,-25.488 -59.731,-25.488 v2(-59.606,-25.613) ; U8.1@-61.306,-19.638 -59.631,-19.638 v2(-59.606,-19.613) ; U8.25@-57.193,-25.594 -57.087,-25.488 U8.15@-55.506,-25.488 ; U8.25@-57.023,-26.162 -56.999,-26.138 U8.14@-55.506,-26.138 -54.126,-26.138 C129.2@-53.908,-26.356 ; v1(-53.891,-26.356) -53.891,-27.643 R28.2@-53.594,-27.94 ; R79.1@-47.414,-17.72 -47.284,-17.59 v1(-46.024,-17.59) ; C30.2@-46.906,-21.022 -46.892,-21.036 C31.2@-45.266,-21.036 ; C73.2@-36.367,-48.752 -35.346,-49.774 v2(-34.648,-49.774) ; C76.2@-36.311,-42.99 -36.311,-41.953 -33.547,-41.953 -33.547,-42.771 C77.2@-33.297,-43.021 ; R72.1@-35.349,-58.868 -36.129,-58.088 -36.129,-56.087 U7.1@-34.716,-54.674 U7.2@-34.081,-54.674 ; R72.1@-35.327,-58.922 -35.327,-59.978 R39.2@-34.795,-60.51 ; R72.1@-35.287,-58.883 C75.2@-33.64,-58.883 ; U7.41@-32.811,-47.174 -32.811,-48.325 U7.45@-32.555,-48.581 ; C21.2@-32.721,-17.954 C22.2@-30.323,-17.954 -28.303,-17.954 C23.2@-27.974,-17.625 -25.857,-17.625 C24.2@-25.529,-17.954 -24.272,-17.954 ; U7.45@-32.555,-48.624 v2(-32.448,-48.624) ; U7.8@-30.271,-54.674 -30.271,-55.535 -30.25,-55.556 -29.764,-55.556 -29.636,-55.685 ; R69.2@-29.636,-57.264 -29.636,-55.685 ; U7.9@-29.636,-54.674 -29.636,-55.685 ; v2(-29.148,-53.224) -29.001,-53.371 U7.10@-29.001,-54.674 -28.945,-54.73 -28.945,-55.535 -29.486,-55.535 -29.636,-55.685 ; U7.35@-29.001,-47.174 -29.001,-48.96 U7.45@-28.872,-49.089 ; C17.1@-26.757,-27.069 C18.1@-26.757,-22.046 ; v1(-26.447,-11.352) -26.447,-11.564 -25.632,-12.379 -23.204,-12.379 U4.8@-23.204,-12.353 -21.777,-12.353 v2(-21.754,-12.375) ; v1(-25.91,-64.714) v1(-25.91,-62.236) -25.91,-60.037 v1(-26.238,-59.709) -26.238,-57.607 v1(-25.91,-57.278) -25.91,-56.337 -25.191,-55.618 ; U7.16@-25.191,-54.674 -25.191,-55.618 ; U7.17@-24.556,-54.674 -24.556,-55.498 -24.503,-55.55 ; U4.17@-23.726,-17.954 -24.272,-17.954 ; v2(-23.648,-53.224) -23.921,-53.496 U7.18@-23.921,-54.674 -23.921,-55.513 -23.884,-55.55 ; U7.19@-23.286,-54.674 -23.286,-55.55 ; U4.22@-23.204,-21.243 -24.171,-21.243 -24.272,-21.142 -24.272,-20.595 ; U4.21@-23.204,-20.608 -24.259,-20.608 -24.272,-20.595 ; U4.20@-23.204,-19.973 -24.188,-19.973 -24.272,-19.889 ; U4.19@-23.204,-19.338 -24.25,-19.338 -24.272,-19.316 ; U4.18@-23.204,-18.703 -23.272,-18.635 -24.272,-18.635 ; U4.17@-23.204,-18.068 -21.947,-18.068 v2(-21.754,-17.875) ; U4.16@-23.204,-17.433 -24.231,-17.433 -24.231,-17.913 -24.272,-17.954 ; U4.10@-23.204,-13.623 -21.902,-13.623 v2(-21.754,-13.475) ; U4.2@-23.204,-8.543 -20.777,-8.543 U4.45@-20.744,-8.576 ; U4.1@-23.204,-7.908 -21.822,-7.908 v2(-21.754,-7.975) ; D1.2@-22.707,-23.623 D1.1@-22.707,-25.703 -22.658,-25.752 C25.2@-22.658,-29.611 -20.66,-29.611 -18.779,-27.73 -13.482,-27.73 C27.2@-13.214,-27.998 -10.404,-27.998 C29.2@-10.401,-28.001 ; U7.20@-22.651,-54.674 -22.651,-55.55 ; U7.21@-22.016,-54.674 -22.016,-55.55 ; C36.2@-17.304,-5.045 -15.843,-6.506 C32.2@-15.704,-6.506 ; v2(-17.154,-13.475) -17.007,-13.623 U4.35@-15.704,-13.623 ; v2(-17.154,-11.275) -16.712,-11.718 U4.38@-15.704,-11.718 ; v2(-17.154,-10.175) -16.756,-10.175 -16.756,-10.142 -16.536,-9.921 -15.812,-9.921 U4.41@-15.704,-9.813 ; D2.1@-16.977,-52.966 D2.2@-19.057,-52.966 -19.673,-52.966 U7.22@-21.381,-54.674 -21.395,-54.688 -21.395,-55.55 -22.016,-55.55 ; C70.2@-13.611,-40.352 -13.662,-40.404 C15.2@-13.662,-47.126 C66.2@-13.662,-56.981 -14.065,-57.383 C58.1@-17.438,-57.383 C59.1@-22.524,-57.383 -23.286,-56.621 -23.286,-55.55 ; v1(-11.738,-8.256) C35.2@-11.738,-6.75 ; -25.191,-55.618 -25.123,-55.55 -24.503,-55.55 ; -24.503,-55.55 -23.884,-55.55 ; -24.272,-20.595 -24.272,-19.889 ; -24.272,-19.889 -24.272,-19.316 ; -24.272,-19.316 -24.272,-18.635 ; -24.272,-18.635 -24.272,-17.954 ; -23.884,-55.55 -23.286,-55.55 ; -23.286,-55.55 -22.651,-55.55 ; -22.651,-55.55 -22.016,-55.55
  Bottom Layer (PAD/SIG) w0.254: C126.2@-51.872,-23.822 -51.867,-23.827 C100.2@-50.142,-23.827 ; U9.6@-42.799,-29.591 -42.612,-29.404 v1(-40.81,-29.404) ; v1@-33.297,-43.021 C74.1@-32.71,-43.021 ; C74.1@-32.57,-43.04 -30.951,-43.04 R75.1@-30.904,-42.993 ; R45.1@-11.813,-11.677 -12.33,-11.16 -12.33,-8.848 v1(-11.738,-8.256)
  other v1: -144.374,-79.737 -144.374,-76.572 -144.374,-73.408 -144.374,-70.288 -144.374,-67.123 -36.31,-60.496 -36.31,-58.855 -13.759,-57.344 -13.783,-56.405 -20.68,-55.71 -19.298,-55.71 -17.916,-55.71 -16.534,-55.71 -20.452,-54.503 -19.07,-54.503 -17.688,-54.503 -16.307,-54.503 -14.925,-54.503 -143.934,-53.661 -13.632,-52.518 -13.656,-51.579 -13.632,-47.438 -5.498,-47.105 -13.656,-46.499 -37.674,-45.675 -13.632,-43.501 -71.678,-43.117 -33.444,-42.993 -29.888,-42.993 -13.656,-42.562 -37.674,-42.484 -71.678,-42.355 -78.148,-41.85 -36.956,-40.962 -35.315,-40.962 -33.673,-40.962 -138.599,-40.36 -135.551,-40.36 -130.979,-40.36 -13.656,-40.276 -132.588,-40.259 -73.396,-40.25 -144.104,-39.767 -142.58,-39.767 -124.278,-38.159 -124.278,-37.151 -44.62,-35.5 -43.223,-35.246 -61.258,-34.88 -125.675,-34.222 -72.828,-34.044 -69.637,-34.044 -66.445,-34.044 -61.257,-33.976 -80.276,-33.55 -132.283,-33.481 -125.675,-33.214 -40.767,-33.147 -43.985,-31.055 -42.461,-31.055 -37.762,-30.928 -46.99,-30.353 -131.339,-29.879 -60.17,-29.664 -23.433,-29.611 -22.051,-29.611 -88.763,-29.582 -68.005,-29.488 -66.363,-29.488 -64.722,-29.488 -137.203,-28.896 -72.179,-28.896 -13.682,-28.261 -12.743,-28.261 -66.401,-28.023 -66.401,-26.382 -121.93,-25.752 -24.219,-25.593 -72.306,-25.467 -50.843,-25.213 -49.954,-25.213 -39.286,-25.086 -63.162,-24.959 -25.13,-24.887 -121.93,-24.552 -24.219,-24.211 -50.208,-23.816 -127.721,-23.765 -25.13,-23.505 -121.93,-23.351 -74.93,-23.368 -76.59,-23.299 -24.219,-22.829 -121.93,-22.151 -25.13,-22.123 -144.442,-21.911 -143.68,-21.657 -43.71,-21.082 -42.436,-21.068 -46.786,-21.019 -45.262,-21.019 -121.93,-20.95 -121.93,-19.75 -31.175,-19.234 -29.793,-19.234 -27.818,-19.234 -25.648,-19.234 -121.849,-16.223 -121.849,-15.022 -127.721,-14.875 -126.197,-14.875 -121.849,-13.822 -30.359,-13.747 -141.19,-13.508 -121.849,-12.621 -121.849,-11.421 -121.836,-10.1 -90.75,-9.849 -27.108,-9.28 -90.75,-8.841 -48.52,-7.451 -46.996,-7.451 -11.727,-6.757 -57.664,-6.588 -50.703,-6.588 -55.349,-6.553 -53.023,-6.526 -127.043,-5.909 -123.487,-5.909 -90.8,-5.763 -63.242,-5.633 -60.303,-5.633 -105.887,-5.587 -26.151,-5.17 -24.769,-5.17 -23.387,-5.17 -22.005,-5.17 -20.623,-5.17 -90.8,-4.755 -105.887,-4.579 -59.163,-4.299 -58.155,-4.299 -52.178,-4.299 -51.17,-4.299 -45.193,-4.299 -44.185,-4.299 -65.409,-4.204 -64.401,-4.204 -36.409,-2.949 -30.124,-2.949 -26.96,-2.949 -21.808,-2.314 -18.617,-2.314 -15.425,-2.314 -12.234,-2.314 -116.31,-2.19 -113.146,-2.19 -110.025,-2.19 -106.861,-2.19 -103.696,-2.19 -100.754,-2.19 -98.214,-2.19 -92.138,-2.187 -88.947,-2.187 -85.755,-2.187 -82.564,-2.187 -79.373,-2.187 -76.182,-2.187 -72.991,-2.187 -69.8,-2.187 -66.609,-2.187 -63.417,-2.187 -60.226,-2.187 -57.035,-2.187 -53.844,-2.187 -50.653,-2.187 -47.462,-2.187 -44.271,-2.187 -41.079,-2.187 -37.888,-2.187 -31.506,-2.187
  other v2: -34.648,-53.224 -33.548,-53.224 -32.448,-53.224 -31.348,-53.224 -30.248,-53.224 -28.048,-53.224 -26.948,-53.224 -25.848,-53.224 -24.748,-53.224 -22.548,-53.224 -21.448,-53.224 -34.648,-52.074 -33.548,-52.074 -32.448,-52.074 -31.348,-52.074 -30.248,-52.074 -29.148,-52.074 -28.048,-52.074 -26.948,-52.074 -25.848,-52.074 -24.748,-52.074 -23.648,-52.074 -22.548,-52.074 -21.448,-52.074 -34.648,-50.924 -33.548,-50.924 -32.448,-50.924 -31.348,-50.924 -30.248,-50.924 -29.148,-50.924 -28.048,-50.924 -26.948,-50.924 -25.848,-50.924 -24.748,-50.924 -23.648,-50.924 -22.548,-50.924 -21.448,-50.924 -33.548,-49.774 -32.448,-49.774 -31.348,-49.774 -30.248,-49.774 -29.148,-49.774 -28.048,-49.774 -26.948,-49.774 -25.848,-49.774 -24.748,-49.774 -23.648,-49.774 -22.548,-49.774 -21.448,-49.774 -34.648,-48.624 -33.548,-48.624 -31.348,-48.624 -30.248,-48.624 -29.148,-48.624 -28.048,-48.624 -26.948,-48.624 -25.848,-48.624 -24.748,-48.624 -23.648,-48.624 -22.548,-48.624 -21.448,-48.624 -59.606,-26.813 -58.406,-26.813 -57.206,-26.813 -58.406,-25.613 -57.206,-25.613 -59.606,-24.413 -58.406,-24.413 -57.206,-24.413 -59.606,-23.213 -58.406,-23.213 -57.206,-23.213 -135.133,-23.154 -133.833,-23.154 -132.533,-23.154 -131.233,-23.154 -135.133,-22.054 -133.833,-22.054 -132.533,-22.054 -59.606,-22.013 -58.406,-22.013 -57.206,-22.013 -21.754,-21.175 -20.604,-21.175 -19.454,-21.175 -18.304,-21.175 -17.154,-21.175 -135.133,-20.954 -133.833,-20.954 -132.533,-20.954 -131.233,-20.954 -59.606,-20.813 -58.406,-20.813 -57.206,-20.813 -21.754,-20.075 -20.604,-20.075 -19.454,-20.075 -18.304,-20.075 -17.154,-20.075 -135.133,-19.854 -133.833,-19.854 -132.533,-19.854 -131.233,-19.854 -58.406,-19.613 -57.206,-19.613 -21.754,-18.975 -20.604,-18.975 -19.454,-18.975 -18.304,-18.975 -17.154,-18.975 -133.833,-18.754 -132.533,-18.754 -131.233,-18.754 -20.604,-17.875 -19.454,-17.875 -18.304,-17.875 -17.154,-17.875 -133.833,-17.654 -132.533,-17.654 -131.233,-17.654 -21.754,-16.775 -20.604,-16.775 -19.454,-16.775 -18.304,-16.775 -17.154,-16.775 -21.754,-15.675 -20.604,-15.675 -19.454,-15.675 -18.304,-15.675 -17.154,-15.675 -133.833,-15.454 -132.533,-15.454 -131.233,-15.454 -21.754,-14.575 -20.604,-14.575 -19.454,-14.575 -18.304,-14.575 -17.154,-14.575 -133.833,-14.354 -132.533,-14.354 -20.604,-13.475 -19.454,-13.475 -18.304,-13.475 -135.133,-13.254 -133.833,-13.254 -132.533,-13.254 -131.233,-13.254 -20.604,-12.375 -19.454,-12.375 -18.304,-12.375 -17.154,-12.375 -133.833,-12.154 -132.533,-12.154 -131.233,-12.154 -21.754,-11.275 -20.604,-11.275 -19.454,-11.275 -18.304,-11.275 -133.833,-11.054 -132.533,-11.054 -131.233,-11.054 -21.754,-10.175 -20.604,-10.175 -19.454,-10.175 -18.304,-10.175 -133.833,-9.954 -132.533,-9.954 -131.233,-9.954 -21.754,-9.075 -20.604,-9.075 -19.454,-9.075 -18.304,-9.075 -17.154,-9.075 -20.604,-7.975 -19.454,-7.975 -18.304,-7.975 -17.154,-7.975
  other v3: -82.153,-29.653 -80.783,-29.653 -83.268,-28.538 -82.153,-28.538 -80.783,-28.538 -79.668,-28.538 -83.268,-27.168 -82.153,-27.168 -80.783,-27.168 -79.668,-27.168 -82.153,-26.053 -80.783,-26.053
SRA: C114.2 D108.1 R114.1 R238.1 | length 6.9
  Top Layer (PADS/SIG) w0.254: C114.2@-142.155,-22.913 R238.1@-140.76,-22.913 -140.76,-24.958 D108.1@-139.997,-25.721 ; D108.1@-139.945,-25.77 -138.522,-25.77 R114.1@-137.965,-25.213 ; R114.1@-138.22,-25.021 R114.1@-138.124,-25.116
SRB: C113.2 D105.1 R113.1 R237.1 | length 12
  Top Layer (PADS/SIG) w0.254: C113.2@-142.155,-21.658 R237.1@-140.76,-21.658 -140.618,-21.658 -140.052,-22.224 -140.052,-23.423 -139.532,-23.943 -134.917,-23.943 R113.1@-134.282,-24.578 ; R113.1@-134.206,-24.883 -133.72,-25.37 D105.1@-133.72,-26.913
SS: C53.2 U6.21 | length 3
  Top Layer (PADS/SIG) w0.254: U6.21@-54.874,-66.443 -54.874,-69 C53.2@-54.585,-69.289
SW_A: D3.2 D9.1 Q101.4 Q102.3 T103.1 T103.2 | length 32.9
  Top Layer (PADS/SIG) w1.524: Q102.3@-111.841,-57.846 -111.841,-52.909 -114.049,-52.909 v1(-114.198,-52.76) -114.198,-47.618 Q101.4@-114.241,-47.574 -114.241,-39.882 -113.462,-39.103 T103.1@-111.287,-39.103 T103.2@-108.107,-39.103
  Bottom Layer (PAD/SIG) w1.524: D9.1@-118.564,-54.526 -118.564,-52.749 -114.209,-52.749 v1(-114.198,-52.76)
SW_B: D4.2 D10.1 L301.1 Q103.4 Q104.3 | length 31.5
  Top Layer (PADS/SIG) w1.524: Q103.4@-97.58,-68.681 v1(-97.58,-63.669) -99.756,-63.669 -100.234,-63.191 Q104.3@-100.234,-58.369 -100.234,-53.055 -99.342,-52.164 L301.1@-94.197,-52.164
  Bottom Layer (PAD/SIG) w1.524: v1(-97.58,-63.669) D10.1@-94.211,-63.669 ; D4.2@-93.96,-66.823 D10.1@-93.96,-63.418
  Bottom Layer (PAD/SIG) w2.286: D10.1@-94.211,-63.669 D10.1@-93.96,-63.418
TCK: "MSP430 JTAG.7" U1.15 | length 76.2
  Top Layer (PADS/SIG) w0.254: v1(-85.908,-26.438) -85.866,-26.438 -85.531,-26.103 U1.15@-84.868,-26.103
  Layer 3 (SIG) w0.254: -136.314,-5.147 -136.314,-8.394 -137.422,-9.502 -137.422,-24.502 -135.928,-25.996 -135.679,-25.996 ; -135.679,-26.006 -127.803,-26.006 -125.171,-28.637 -93.165,-28.637 -89.656,-25.128 -87.259,-25.128 -85.95,-26.438 v1(-85.908,-26.438)
TDI: "MSP430 JTAG.3" U1.13 | length 78.3
  Top Layer (PADS/SIG) w0.254: v1(-85.908,-24.878) -85.709,-25.077 -84.894,-25.077 U1.13@-84.868,-25.103
  Layer 3 (SIG) w0.254: -135.552,-25.088 -127.437,-25.088 -124.795,-27.729 -93.541,-27.729 -89.959,-24.147 -86.639,-24.147 v1(-85.908,-24.878) ; -135.552,-25.086 -136.514,-24.124 -136.514,-9.878 -135.56,-8.923 -131.969,-8.923 -131.234,-8.188 -131.234,-5.147
TDO: "MSP430 JTAG.1" U1.12 | length 79.7
  Top Layer (PADS/SIG) w0.254: U1.12@-84.218,-24.453 -84.218,-23.728 v1(-84.082,-23.592)
  Layer 3 (SIG) w0.254: -135.298,-24.634 -127.083,-24.634 -124.441,-27.275 -93.729,-27.275 -90.147,-23.693 -84.183,-23.693 v1@-84.088,-23.598 ; -135.234,-24.57 -136.06,-23.745 -136.06,-10.066 -135.372,-9.377 -131.781,-9.377 -128.694,-6.29 -128.694,-5.147
TEST: "MSP430 JTAG.8" U1.22 | length 81.8
  Top Layer (PADS/SIG) w0.254: v1(-87.211,-26.483) -87.211,-28.342 -85.95,-29.603 U1.22@-84.868,-29.603
  Layer 3 (SIG) w0.254: -136.187,-2.607 -136.557,-2.977 -136.557,-3.761 -137.466,-4.67 -137.466,-8.903 -137.876,-9.313 -137.876,-24.69 -136.106,-26.46 -127.991,-26.46 -125.359,-29.091 -92.977,-29.091 -89.468,-25.582 -88.112,-25.582 v1(-87.211,-26.483)
THERM: R21.2 U1.34 U3.7 | length 6.9
  Top Layer (PADS/SIG) w0.254: -80.692,-33.083 -79.718,-32.109 U1.34@-79.718,-31.253 ; -80.688,-33.087 -80.942,-33.341 -80.942,-34.103 -80.709,-34.336 U3.7@-79.291,-34.336 ; U3.7@-79.114,-34.313 -77.59,-34.313 R21.2@-77.392,-34.511
THERM2: R20.2 U1.35 U3.10 | length 3.3
  Top Layer (PADS/SIG) w0.254: U3.10@-79.218,-32.779 U1.35@-79.218,-31.253 ; U3.10@-79.114,-32.813 -77.533,-32.813 -77.507,-32.839 R20.2@-77.386,-32.96
TMS: "MSP430 JTAG.5" U1.14 | length 76.7
  Top Layer (PADS/SIG) w0.254: v1(-85.908,-25.658) -85.853,-25.603 U1.14@-84.868,-25.603
  Layer 3 (SIG) w0.254: -134.79,-8.469 -135.748,-8.469 -136.968,-9.69 -136.968,-24.314 -135.74,-25.542 -127.625,-25.542 -124.983,-28.183 -93.353,-28.183 -89.771,-24.601 -87.007,-24.601 -85.95,-25.658 v1(-85.908,-25.658) ; -134.79,-8.449 -133.774,-7.433 -133.774,-5.147
UART_CTS: "MSP430 JTAG.10" UART/D.1 | length 29.2
  Layer 3 (SIG) w0.254: UART/D.1@-143.553,-24.832 -142.791,-24.07 -139.87,-24.07 -139.362,-23.562 -139.362,-8.808 -142.546,-5.624 -142.546,-4.648 -141.902,-4.004 ; -141.902,-3.995 -140.496,-3.995 -139.108,-2.607
UART_RTS: "MSP430 JTAG.13" UART/R.1 | length 35.7
  Layer 3 (SIG) w0.254: -143.934,-5.147 -139.816,-9.265 -139.816,-12.132 ; UART/R.1@-143.553,-32.833 -143.553,-31.541 -142.401,-30.389 -142.401,-29.658 ; -143.553,-23.616 -140.058,-23.616 -139.87,-23.428 -139.87,-12.132 ; -143.553,-23.562 -144.696,-24.705 -144.705,-24.705 -144.705,-27.602 -143.958,-28.349 -142.703,-28.349 -142.41,-28.642 -142.41,-29.658
VG_HOA: Q101.1 R208.1 R209.1 R212.1 | length 6.8
  Top Layer (PADS/SIG) w1.016: R212.1@-118.603,-49.41 -118.754,-49.259 -118.754,-46.271 -117.187,-44.704 Q101.1@-115.842,-44.704
VG_HOB: Q103.1 R221.1 R222.1 R225.1 | length 6.1
  Top Layer (PADS/SIG) w0.9: Q103.1@-95.979,-71.551 -94.828,-70.4 R221.1@-93.445,-70.4 ; R225.1@-93.485,-68.869 -93.445,-68.909 R221.1@-93.445,-70.4 ; R222.1@-93.445,-71.948 R221.1@-93.445,-70.4
VG_LOA: Q102.1 R210.1 R211.1 R213.1 | length 6
  Top Layer (PADS/SIG) w1.016: R211.1@-118.689,-53.915 -118.564,-54.04 R210.1@-118.564,-55.41 ; R210.1@-118.641,-55.41 R210.1@-118.564,-55.41 ; R213.1@-118.564,-56.91 R210.1@-118.564,-55.41 ; Q102.1@-115.842,-54.976 -116.276,-55.41 R210.1@-118.564,-55.41
VG_LOB: Q104.1 R223.1 R224.1 R226.1 | length 6.5
  Top Layer (PADS/SIG) w1.016: Q104.1@-96.233,-61.239 -94.564,-62.908 R223.1@-93.445,-62.908 ; R226.1@-93.485,-61.369 -93.445,-61.409 R223.1@-93.445,-62.908 ; R224.1@-93.445,-64.408 R223.1@-93.445,-62.908
VG_SRA: Q106.1 R231.1 R232.1 R235.1 | length 7.6
  Top Layer (PADS/SIG) w1.016: R235.1@-126.376,-13.285 R235.1@-126.183,-13.091 ; R231.1@-126.218,-11.828 -126.197,-11.807 R232.1@-126.197,-10.304 ; R235.1@-126.183,-13.343 R235.1@-126.183,-13.091 ; -126.183,-11.368 R235.1@-126.183,-13.091 ; Q106.1@-123.477,-10.386 R235.1@-126.183,-13.091
VG_SRB: Q105.1 R233.1 R234.1 R236.1 | length 5.8
  Top Layer (PADS/SIG) w1.016: R233.1@-126.189,-19.354 R233.1@-126.183,-19.361 ; R234.1@-126.189,-17.905 -126.183,-17.911 R233.1@-126.183,-19.361 ; R236.1@-126.183,-20.843 R233.1@-126.183,-19.361 ; Q105.1@-123.531,-19.736 -125.808,-19.736 R233.1@-126.183,-19.361
VIN: C7.1 C8.1 C9.1 C10.1 C11.1 C12.1 C13.1 C19.1 C20.1 C38.1 C39.1 C40.1 C41.1 C102.1 C103.1 C107.1 C108.1 L3.2 Q1.3 R46.2 R49.2 T1.5 T102.1 VIN_28V.1 | length 12.5
  Top Layer (PADS/SIG) w0.508: R46.2@-67.642,-62.122 -67.489,-62.122 -66.88,-62.732 ; v1(-67.134,-59.415) -66.806,-59.415 -66.669,-59.552 -66.083,-60.138 ; Q1.3@-66.88,-63.513 -66.88,-62.732 ; -66.25,-60.247 -66.807,-59.69 -66.807,-62.659 -66.88,-62.732 ; -66.083,-60.247 -64.619,-60.247 -63.451,-61.416 v1(-63.451,-63.748)
  other v1: -75.825,-79.159 -71.101,-79.159 -80.653,-79.095 -36.926,-78.834 -78.211,-78.109 -73.777,-78.109 -100.087,-77.815 -98.59,-77.815 -96.552,-77.815 -95.055,-77.815 -93.102,-77.815 -91.604,-77.815 -89.546,-77.815 -88.048,-77.815 -61.597,-77.775 -60.099,-77.775 -58.144,-77.775 -56.646,-77.775 -54.691,-77.775 -53.193,-77.775 -51.238,-77.775 -49.74,-77.775 -47.785,-77.775 -46.287,-77.775 -44.332,-77.775 -42.835,-77.775 -40.879,-77.775 -39.382,-77.775 -36.926,-77.336 -114.645,-76.595 -80.653,-76.608 -75.78,-76.608 -71.101,-76.608 -53.85,-75.963 -49.126,-75.963 -93.986,-75.924 -89.262,-75.924 -58.679,-75.898 -98.815,-75.859 -78.211,-75.483 -73.777,-75.483 -114.645,-75.097 -56.237,-74.913 -51.802,-74.913 -96.373,-74.874 -91.938,-74.874 -110.253,-74.296 -108.755,-74.296 -104.98,-74.296 -103.482,-74.296 -58.679,-73.412 -53.805,-73.412 -49.126,-73.412 -56.237,-72.287 -51.802,-72.287 -66.88,-63.503 -67.734,-62.17 -68.142,-59.415 -50.818,-52.452 -53.801,-51 -53.801,-49.992 -50.807,-49.899 -50.786,-47.314
VLDO: C42.1 R50.2 U6.8 U6.9 U6.10 | length 8.7
  Top Layer (PADS/SIG) w0.254: R50.2@-61.763,-63.584 -61.501,-63.584 -60.726,-62.809 -60.726,-58.868 ; -60.749,-58.868 -60.749,-58.504 -60.441,-58.196 -59.008,-58.196 C42.1@-58.206,-58.998
VS_HOA: C203.2 C204.2 D202.2 Q101.5 R212.2 U201.1 U201.2 U201.3 U201.4 U201.5 U201.6 U201.7 U201.9 U201.10 U201.11 U201.12 U201.13 U201.44 U201.45 U201.46 U201.47 U201.57 | length 52.1
  Top Layer (PADS/SIG) w0.254: C203.2@-131.366,-48.723 -131.366,-48.82 -130.314,-49.871 U201.57@-126.439,-49.871 ; U201.13@-129.314,-51.871 -127.309,-51.871 U201.57@-127.297,-51.883 ; U201.12@-129.314,-51.371 U201.57@-127.939,-51.371 ; U201.11@-129.314,-50.871 U201.57@-127.439,-50.871 ; U201.10@-129.314,-50.371 U201.57@-126.939,-50.371 ; U201.7@-129.314,-48.871 U201.57@-125.689,-48.871 ; U201.6@-129.314,-48.371 U201.57@-126.189,-48.371 ; U201.5@-129.314,-47.871 U201.57@-126.689,-47.871 ; U201.4@-129.314,-47.371 U201.57@-127.189,-47.371 ; U201.3@-129.314,-46.871 -127.689,-46.871 U201.57@-127.189,-47.371 ; U201.2@-129.265,-46.359 -127.766,-46.359 U201.57@-127.762,-46.355 ; U201.1@-128.689,-45.871 -128.113,-45.871 U201.57@-128.034,-45.951 ; D202.2@-125.051,-43.714 -124.376,-44.39 U201.57@-124.376,-46.295 ; U201.44@-121.814,-51.871 -120.677,-51.871 -120.677,-51.446 ; U201.45@-121.814,-51.371 -120.752,-51.371 -120.677,-51.446 ; U201.46@-121.814,-50.871 -120.803,-50.871 -120.799,-50.867 -120.677,-50.867 ; C204.2@-120.058,-50.867 -120.677,-50.867 ; U201.57@-127.189,-47.371 U201.57@-126.689,-47.871 ; U201.57@-126.689,-47.871 U201.57@-126.189,-48.371 ; U201.57@-126.189,-48.371 U201.57@-125.689,-48.871 ; U201.57@-125.689,-48.871 -124.189,-50.371 -121.814,-50.371 -121.793,-50.35 -120.677,-50.35 -120.677,-50.867 ; -120.677,-51.446 -120.677,-50.867
  Top Layer (PADS/SIG) w1.016: C204.2@-119.77,-50.833 R212.2@-118.603,-50.833 -117.34,-50.833 -117.007,-50.499 -117.007,-49.089 -116.563,-48.644 -115.842,-48.644 Q101.5@-115.842,-47.574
